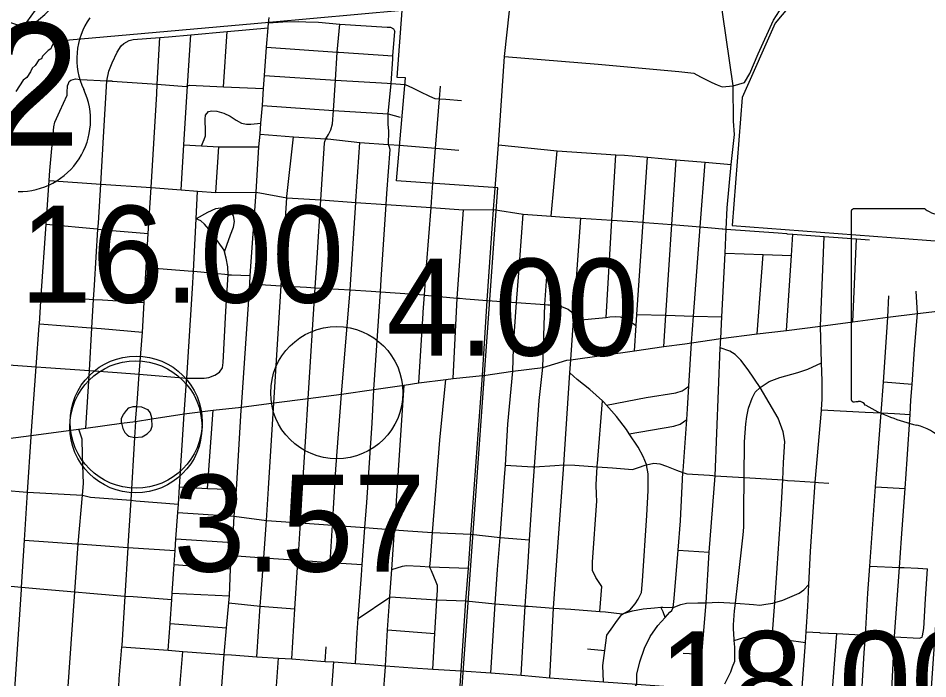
# Model space of a CAD drawing. Extents: x 1729596 to 1934326, y 644115 to 911751.
# Drawn here: x 1844605 to 1854923, y 714700 to 722193 of the extents above; entities that cross this region are included whole.
import ezdxf

# ---------------------------------------------------------------- set-up
doc = ezdxf.new("R2010")
doc.units = 0
for name, color, linetype in [('Default', 7, 'Continuous'), ('GM_X_City_Street', 7, 'Continuous'), ('GM_X_Corporation', 7, 'Continuous'), ('GM_X_Interstate_Route', 7, 'Continuous'), ('GM_X_State_Route', 7, 'Continuous'), ('GM_X_State_Shield', 7, 'Continuous'), ('GM_X_Township', 7, 'Continuous'), ('GM_X_US_Route', 7, 'Continuous'), ('GM_X_US_Shield', 7, 'Continuous')]:
    doc.layers.add(name, color=color, linetype=linetype)

msp = doc.modelspace()

# ---------------------------------------------------------------- linework, layer by layer
at = {"layer": 'Default'}
for centre in [(1848219, 717945), (1845943, 717611), (1845940, 717558)]:
    msp.add_circle(centre, 750, dxfattribs=at)
at = {"layer": 'GM_X_City_Street'}
for points in [[(1844681, 722118), (1844702, 722148), (1844900, 722425), (1844915, 722447), (1845042, 722635)], [(1852692, 720534), (1852732, 720874), (1852718, 721026), (1852717, 721427), (1852558, 722528)], [(1852717, 721427), (1852843, 721465), (1852904, 721564), (1852998, 721790), (1853173, 722172), (1853242, 722278), (1853303, 722358)], [(1844371, 722188), (1844574, 722127), (1844617, 722116), (1844681, 722118)], [(1847136, 717748), (1847138, 717780), (1847221, 719001), (1847231, 719179), (1847238, 719273), (1847303, 720218), (1847336, 720734), (1847351, 720879), (1847356, 721002), (1847375, 721204), (1847386, 721394), (1847399, 721545), (1847420, 721866), (1847442, 722083), (1847446, 722139), (1847451, 722196), (1847452, 722201)], [(1845863, 721939), (1845911, 721951), (1846211, 721973), (1846310, 721980), (1846564, 722004), (1846977, 722043), (1847442, 722083)], [(1847446, 722139), (1847607, 722150), (1847783, 722155), (1847869, 722153), (1848010, 722147), (1848254, 722126), (1848791, 722092), (1848827, 722091), (1848864, 722072), (1848878, 722043)], [(1848085, 720793), (1848094, 720826), (1848123, 720875), (1848152, 720925), (1848170, 720994), (1848181, 721145), (1848204, 721491), (1848225, 721808), (1848254, 722126)], [(1845953, 717827), (1845978, 718154), (1846015, 718631), (1846035, 718969), (1846058, 719366), (1846080, 719750), (1846115, 720271), (1846176, 721336), (1846182, 721443), (1846211, 721973)], [(1846452, 720248), (1846485, 720756), (1846527, 721426), (1846564, 722004)], [(1846932, 721415), (1846977, 722043)], [(1848854, 721731), (1848856, 721765), (1848878, 722043)], [(1845374, 717543), (1845413, 718196), (1845441, 718681), (1845461, 719004), (1845470, 719165), (1845510, 719801), (1845514, 719870), (1845541, 720311), (1845574, 720842), (1845612, 721484), (1845633, 721594), (1845670, 721688), (1845727, 721808), (1845773, 721879), (1845802, 721906), (1845863, 721939)], [(1847420, 721866), (1848225, 721808), (1848241, 721806)], [(1848241, 721806), (1848856, 721765)], [(1850016, 720267), (1850052, 720757), (1850121, 721758)], [(1850121, 721758), (1851183, 721671), (1852098, 721588), (1852268, 721570), (1852345, 721527), (1852473, 721462), (1852532, 721436), (1852590, 721416), (1852717, 721427)], [(1848812, 720742), (1848811, 720744), (1848809, 720753), (1848807, 720759), (1848811, 720910), (1848803, 720991), (1848803, 721108), (1848835, 721453), (1848854, 721731)], [(1844955, 720352), (1844965, 720464), (1845009, 720961), (1845020, 721012), (1845076, 721139), (1845161, 721321), (1845162, 721351), (1845166, 721425), (1845175, 721453), (1845185, 721475), (1845202, 721490), (1845256, 721507)], [(1845256, 721507), (1845312, 721499), (1845612, 721484), (1845656, 721481), (1845666, 721481), (1845672, 721480)], [(1845672, 721480), (1846182, 721443), (1846511, 721419), (1846527, 721426), (1846549, 721434), (1846932, 721415), (1847386, 721394)], [(1847399, 721545), (1848204, 721491), (1848789, 721456)], [(1848789, 721456), (1848835, 721453), (1848994, 721442)], [(1848994, 721442), (1849077, 721403), (1849162, 721360), (1849271, 721307), (1849332, 721283), (1849384, 721279), (1849456, 721274), (1849634, 721259)], [(1849307, 720321), (1849339, 720719), (1849384, 721279), (1849396, 721424)], [(1846685, 720744), (1846713, 720816), (1846729, 720860), (1846728, 720908), (1846724, 721046), (1846731, 721092), (1846765, 721135), (1846803, 721142), (1846857, 721139), (1846936, 721115), (1847009, 721080), (1847078, 721038), (1847139, 721003), (1847193, 720991), (1847243, 720990), (1847356, 721002)], [(1847375, 721204), (1848181, 721145), (1848803, 721108), (1848939, 721072)], [(1847351, 720879), (1847728, 720849), (1848094, 720826), (1848116, 720823)], [(1847504, 717831), (1847589, 719157), (1847589, 719159), (1847653, 720157), (1847654, 720169), (1847728, 720849)], [(1846485, 720756), (1846685, 720744), (1846879, 720733), (1847336, 720734)], [(1846848, 720217), (1846879, 720733)], [(1847894, 717880), (1847974, 719135), (1847996, 719475), (1848038, 720131), (1848080, 720775), (1848085, 720793)], [(1848116, 720823), (1848480, 720782), (1848803, 720759), (1848807, 720759), (1848931, 720752)], [(1848435, 720107), (1848435, 720117), (1848480, 720782)], [(1848640, 717983), (1848714, 719090), (1848723, 719230), (1848779, 720080), (1848787, 720204), (1848823, 720702), (1848812, 720742)], [(1848931, 720752), (1849339, 720719), (1849604, 720698)], [(1850052, 720757), (1850720, 720687), (1851385, 720644), (1851481, 720638), (1851742, 720615), (1852070, 720587), (1852396, 720559), (1852692, 720534)], [(1850652, 719946), (1850720, 720687)], [(1851343, 719959), (1851343, 719959), (1851385, 720644)], [(1851697, 719936), (1851697, 719936), (1851742, 720615)], [(1851930, 718468), (1851953, 718823), (1852021, 719852), (1852070, 720587)], [(1852241, 718512), (1852264, 718814), (1852341, 719825), (1852396, 720559)], [(1852570, 718492), (1852572, 718519), (1852574, 718560), (1852586, 718804), (1852623, 719527), (1852637, 719801), (1852649, 720043), (1852692, 720534)], [(1844752, 717444), (1844753, 717461), (1844810, 718238), (1844844, 718706), (1844846, 718726), (1844867, 719046), (1844922, 719856), (1844955, 720352)], [(1844955, 720352), (1845541, 720311), (1846115, 720271), (1846452, 720248), (1846640, 720233), (1846848, 720217), (1847303, 720218)], [(1849294, 720111), (1849294, 720112), (1849307, 720321)], [(1846514, 718074), (1846516, 718110), (1846584, 719128), (1846593, 719322), (1846624, 719917), (1846640, 720233)], [(1847303, 720218), (1847653, 720157), (1848038, 720131), (1848435, 720104), (1848779, 720080), (1849290, 720045), (1849657, 720020), (1849998, 720023)], [(1849872, 718141), (1849926, 718992), (1849998, 720023), (1850016, 720267)], [(1848272, 717930), (1848370, 719111), (1848435, 720104), (1848435, 720107)], [(1849238, 719374), (1849238, 719381), (1849290, 720045), (1849294, 720111)], [(1846945, 719543), (1846970, 719620), (1847013, 719735), (1847048, 719824), (1847058, 719886), (1847046, 719952), (1847019, 719995), (1846987, 720018), (1846954, 720033), (1846902, 720039), (1846844, 720032), (1846754, 719991), (1846624, 719917)], [(1849538, 718108), (1849586, 719019), (1849657, 720020)], [(1849998, 720023), (1850334, 719971), (1850652, 719946), (1850799, 719935), (1850987, 719923), (1851340, 719901), (1851693, 719879), (1851715, 719877), (1852021, 719852), (1852341, 719825), (1852470, 719814), (1852590, 719805), (1852598, 719804)], [(1846516, 718110), (1846632, 718110), (1846714, 718110), (1846766, 718118), (1846837, 718144), (1846888, 718179), (1846923, 718228), (1846931, 718288), (1846962, 718870), (1846986, 719285), (1846983, 719373), (1846965, 719470), (1846945, 719543), (1846940, 719561), (1846873, 719657), (1846794, 719769), (1846719, 719858), (1846678, 719895), (1846624, 719917)], [(1850294, 719447), (1850295, 719457), (1850334, 719971)], [(1850873, 718319), (1850905, 718763), (1850987, 719923)], [(1851273, 718800), (1851340, 719901), (1851343, 719959)], [(1851596, 718421), (1851615, 718709), (1851624, 718834), (1851693, 719879), (1851697, 719936)], [(1844922, 719856), (1845501, 719802)], [(1845501, 719802), (1845503, 719802), (1845510, 719801), (1845582, 719794), (1846080, 719750)], [(1852598, 719804), (1852637, 719801), (1853225, 719757), (1853319, 719750), (1853326, 719749)], [(1853319, 718652), (1853376, 719500), (1853393, 719744)], [(1853326, 719749), (1853393, 719744), (1853749, 719718), (1854114, 719690), (1854263, 719679)], [(1853705, 718700), (1853749, 719718)], [(1854074, 718749), (1854114, 719690)], [(1852623, 719527), (1853056, 719511), (1853376, 719500)], [(1852988, 718611), (1853056, 719511)], [(1850222, 718452), (1850222, 718481), (1850259, 718970), (1850294, 719447)], [(1850555, 718232), (1850579, 718947), (1850612, 719423)], [(1846058, 719366), (1846582, 719323), (1846593, 719322), (1846594, 719322)], [(1846594, 719322), (1846677, 719316), (1846986, 719285), (1846992, 719284), (1847003, 719284), (1847023, 719283)], [(1847023, 719283), (1847238, 719273)], [(1849198, 718847), (1849199, 718859), (1849213, 719054), (1849238, 719374)], [(1847231, 719179), (1847589, 719157), (1847874, 719141), (1847974, 719135), (1848370, 719111), (1848610, 719097), (1848714, 719090), (1849213, 719054), (1849219, 719053), (1849586, 719019), (1849597, 719018), (1849609, 719017)], [(1854805, 718842), (1854792, 719098)], [(1844867, 719046), (1845461, 719004), (1845563, 718997), (1846035, 718969)], [(1849609, 719017), (1849682, 719010), (1849926, 718992)], [(1849926, 718992), (1850259, 718970), (1850579, 718947), (1850582, 718947), (1850613, 718943), (1850631, 718940)], [(1854469, 718802), (1854481, 719044)], [(1850631, 718940), (1850668, 718934), (1850756, 718926), (1850843, 718891), (1850886, 718858), (1850905, 718763), (1851273, 718800), (1851315, 718804), (1851375, 718810), (1851435, 718807), (1851510, 718774), (1851615, 718709)], [(1849150, 718057), (1849198, 718847)], [(1851624, 718834), (1851953, 718823), (1852264, 718814), (1852586, 718804)], [(1854170, 714483), (1854202, 714993), (1854215, 715195), (1854244, 715671), (1854265, 715979), (1854331, 716879), (1854393, 717715), (1854393, 717717), (1854422, 718065), (1854469, 718802)], [(1854397, 712816), (1854440, 713426), (1854449, 713558), (1854471, 713904), (1854506, 714424), (1854546, 715177), (1854546, 715183), (1854601, 715963), (1854624, 716297), (1854666, 716858), (1854690, 717192), (1854722, 717698), (1854732, 717860), (1854745, 718038), (1854774, 718438), (1854805, 718842)], [(1844846, 718726), (1845429, 718682), (1845431, 718682)], [(1845431, 718682), (1845441, 718681), (1845546, 718673), (1846015, 718631)], [(1853332, 713071), (1853334, 713085), (1853400, 713513), (1853435, 713744), (1853452, 713957), (1853492, 714498), (1853536, 715110), (1853544, 715232), (1853563, 715520), (1853574, 715770), (1853591, 716145), (1853644, 716930), (1853716, 717743), (1853716, 717751), (1853725, 717875), (1853725, 718079), (1853719, 718283), (1853705, 718700)], [(1852034, 715508), (1852047, 715612), (1852090, 716158), (1852116, 716492), (1852146, 717041), (1852147, 717059), (1852188, 717640), (1852197, 717763), (1852212, 718019), (1852241, 718512)], [(1852193, 712911), (1852193, 712911), (1852252, 713596), (1852333, 714585), (1852361, 714976), (1852409, 715561), (1852442, 716135), (1852511, 717004), (1852568, 718454), (1852570, 718492)], [(1853156, 715168), (1853187, 715565), (1853192, 715623), (1853259, 716622), (1853277, 716955), (1853288, 717154), (1853301, 717392), (1853282, 717503), (1853225, 717655), (1853023, 718003), (1852884, 718206), (1852802, 718314), (1852739, 718380), (1852678, 718416), (1852568, 718454)], [(1842933, 718358), (1844447, 718264), (1844810, 718238), (1844918, 718230), (1845413, 718196), (1845727, 718175), (1845978, 718154), (1846516, 718110)], [(1850216, 718190), (1850222, 718452)], [(1850635, 714711), (1850676, 715502), (1850713, 715988), (1850793, 717127), (1850805, 717306), (1850862, 718172), (1850873, 718319)], [(1853023, 718003), (1853125, 718071), (1853244, 718119), (1853448, 718174), (1853561, 718212), (1853719, 718283)], [(1849965, 714766), (1850014, 715550), (1850043, 715939), (1850071, 716303), (1850123, 716985), (1850132, 717123), (1850161, 717589), (1850216, 718190)], [(1850310, 714742), (1850340, 715271), (1850356, 715525), (1850388, 716023), (1850404, 716277), (1850445, 716897), (1850460, 717104), (1850513, 717857), (1850555, 718232)], [(1851243, 714665), (1851236, 714852), (1851260, 715021), (1851284, 715195), (1851349, 715291), (1851391, 715350), (1851451, 715429), (1851473, 715441), (1851543, 715480), (1851603, 715551), (1851638, 715604), (1851674, 715679), (1851686, 715811), (1851736, 716553), (1851752, 716835), (1851751, 716946), (1851750, 717026), (1851733, 717128), (1851733, 717131), (1851693, 717222), (1851638, 717326), (1851537, 717478), (1851504, 717528), (1851392, 717674), (1851277, 717804), (1851239, 717846), (1851233, 717852), (1851091, 717983), (1850946, 718096), (1850862, 718172)], [(1846489, 717706), (1846514, 718074)], [(1849310, 714808), (1849332, 715214), (1849354, 715596), (1849360, 715704), (1849361, 715760), (1849348, 715795), (1849292, 715926), (1849275, 715963), (1849276, 715969), (1849282, 716051), (1849306, 716359), (1849389, 717405), (1849454, 718095)], [(1849508, 713010), (1849533, 713412), (1849555, 713758), (1849581, 714093), (1849583, 714126), (1849607, 714451), (1849629, 714791), (1849684, 715585), (1849714, 715954), (1849739, 716340), (1849872, 718141)], [(1854745, 718038), (1854422, 718065)], [(1848537, 716414), (1848537, 716415), (1848558, 716699), (1848622, 717598), (1848640, 717983)], [(1848673, 713046), (1848673, 713047), (1848705, 713425), (1848705, 713426), (1848708, 713773), (1848708, 713794), (1848725, 714152), (1848730, 714259), (1848746, 714487), (1848770, 714837), (1848771, 714847), (1848796, 715255), (1848819, 715627), (1848819, 715633), (1848842, 715938), (1848874, 716390), (1848889, 716600), (1848926, 717180), (1848982, 718032)], [(1851277, 717804), (1851727, 717891), (1852066, 717943), (1852135, 717967), (1852170, 717990), (1852212, 718019)], [(1852619, 714643), (1852687, 714778), (1852707, 714837), (1852733, 714901), (1852733, 714975), (1852733, 715057), (1852728, 715133), (1852728, 715146), (1852719, 715272), (1852718, 715312), (1852729, 715472), (1852742, 715556), (1852770, 715794), (1852828, 716333), (1852835, 716421), (1852836, 716616), (1852839, 716976), (1852839, 716985), (1852843, 717387), (1852857, 717593), (1852869, 717677), (1852890, 717771), (1852931, 717882), (1852963, 717951), (1853023, 718003)], [(1847777, 716024), (1847779, 716045), (1847806, 716468), (1847823, 716745), (1847869, 717447), (1847894, 717880)], [(1848170, 716442), (1848209, 717078), (1848272, 717930)], [(1851173, 717118), (1851173, 717120), (1851175, 717141), (1851233, 717852)], [(1845778, 717598), (1845778, 717656), (1845801, 717699), (1845835, 717744), (1845860, 717774), (1845910, 717788), (1845950, 717789), (1846004, 717786), (1846071, 717754), (1846102, 717717), (1846111, 717692), (1846121, 717649)], [(1845937, 717620), (1845950, 717789), (1845953, 717827)], [(1846754, 716857), (1846818, 717746)], [(1846836, 713122), (1846840, 713500), (1846863, 713873), (1846886, 714244), (1846887, 714257), (1846915, 714615), (1846942, 714976), (1846966, 715278), (1846996, 715563), (1847001, 715640), (1847015, 715946), (1847031, 716098), (1847038, 716245), (1847054, 716543), (1847080, 716846), (1847136, 717748)], [(1847311, 714951), (1847351, 715524), (1847361, 715666), (1847390, 716073), (1847416, 716446), (1847420, 716496), (1847444, 716860), (1847504, 717831)], [(1853716, 717751), (1854211, 717723), (1854393, 717715), (1854547, 717709), (1854722, 717698)], [(1845778, 717598), (1845791, 717539), (1845814, 717493), (1845841, 717466), (1845860, 717451), (1845926, 717437), (1846010, 717443), (1846067, 717477), (1846109, 717522), (1846126, 717564), (1846121, 717649)], [(1846308, 715024), (1846329, 715327), (1846348, 715598), (1846353, 715673), (1846375, 715997), (1846386, 716155), (1846395, 716289), (1846416, 716585), (1846422, 716681), (1846436, 716879), (1846489, 717706)], [(1851537, 717478), (1852043, 717565), (1852114, 717587), (1852151, 717616), (1852188, 717640)], [(1845118, 713864), (1845247, 715686), (1845274, 716069), (1845285, 716229), (1845335, 716782), (1845345, 716914), (1845339, 717125), (1845333, 717241), (1845329, 717419), (1845294, 717532)], [(1844472, 713184), (1844520, 713906), (1844642, 715713), (1844644, 715740), (1844677, 716273), (1844712, 716818), (1844752, 717444)], [(1850132, 717123), (1850443, 717104), (1850450, 717104)], [(1850450, 717104), (1850453, 717104), (1850460, 717104), (1850694, 717121), (1850793, 717127), (1850798, 717128), (1850920, 717122), (1851172, 717105), (1851345, 717094), (1851573, 717075), (1851629, 717092), (1851728, 717127), (1851733, 717128), (1851817, 717146), (1851883, 717140), (1851958, 717112), (1852071, 717067), (1852146, 717041), (1852190, 717025), (1852446, 717009), (1852483, 717006)], [(1851204, 715463), (1851224, 715746), (1851157, 715850), (1851121, 715928), (1851120, 716024), (1851168, 716720), (1851164, 716786), (1851160, 716905), (1851172, 717105), (1851173, 717118)], [(1852483, 717006), (1852511, 717004), (1852839, 716985), (1852843, 716984), (1853277, 716955), (1853282, 716955), (1853330, 716951)], [(1853330, 716951), (1853412, 716946), (1853644, 716930), (1853683, 716927)], [(1853683, 716927), (1853802, 716919)], [(1844439, 716839), (1844707, 716818)], [(1844707, 716818), (1844707, 716818), (1844712, 716818), (1845335, 716782), (1845426, 716762), (1845881, 716725), (1845940, 716720)], [(1846436, 716879), (1846754, 716857), (1847080, 716846)], [(1854331, 716879), (1854666, 716858)], [(1845940, 716720), (1845940, 716720), (1846422, 716681)], [(1846416, 716585), (1847049, 716543)], [(1847049, 716543), (1847054, 716543), (1847420, 716496), (1847806, 716468), (1848170, 716442), (1848274, 716435), (1848537, 716415), (1848874, 716390), (1849025, 716379), (1849306, 716359), (1849739, 716340)], [(1848142, 716020), (1848170, 716442)], [(1848431, 714872), (1848451, 715227), (1848463, 715383), (1848498, 715877), (1848507, 715995), (1848537, 716414)], [(1846395, 716289), (1847038, 716245)], [(1849739, 716340), (1850071, 716303), (1850404, 716277)], [(1844677, 716273), (1845265, 716231)], [(1845265, 716231), (1845265, 716231), (1845285, 716229), (1845848, 716191), (1846386, 716155)], [(1847031, 716098), (1847390, 716073), (1847779, 716045), (1847841, 716041), (1848142, 716020), (1848507, 715995)], [(1852090, 716158), (1852442, 716135)], [(1846375, 715997), (1847015, 715946)], [(1847708, 714925), (1847744, 715494), (1847777, 716024)], [(1848842, 715938), (1848963, 715978), (1849008, 715987), (1849166, 715978), (1849276, 715969), (1849714, 715954)], [(1854265, 715979), (1854601, 715963), (1854646, 715961), (1854654, 715961)], [(1854654, 715961), (1854809, 715953), (1854812, 715953)], [(1854812, 715953), (1854918, 715948)], [(1854860, 715174), (1854862, 715186), (1854877, 715272), (1854897, 715607), (1854918, 715948)], [(1844359, 715765), (1844644, 715740), (1844852, 715722), (1845247, 715686), (1845418, 715670), (1845814, 715639), (1845910, 715632), (1846348, 715598)], [(1846353, 715673), (1847001, 715640)], [(1850389, 715523), (1850676, 715502), (1850874, 715488), (1851204, 715463), (1851268, 715458), (1851457, 715437), (1851473, 715441), (1851572, 715470), (1851695, 715492), (1851824, 715506), (1851893, 715512), (1851918, 715514), (1852034, 715508), (1852121, 715542), (1852185, 715556), (1852313, 715562), (1852409, 715561), (1852546, 715568), (1852742, 715556), (1852746, 715556), (1852947, 715542), (1853019, 715536), (1853085, 715546), (1853164, 715558), (1853187, 715565), (1853279, 715593), (1853463, 715672), (1853516, 715708), (1853574, 715770)], [(1848463, 715383), (1848819, 715627), (1848825, 715631), (1849354, 715596), (1849684, 715585)], [(1849684, 715585), (1850014, 715550), (1850356, 715525), (1850370, 715524), (1850389, 715523)], [(1846996, 715563), (1847351, 715524), (1847744, 715494)], [(1851602, 714585), (1851606, 714616), (1851621, 714638), (1851624, 714753), (1851656, 714892), (1851708, 715049), (1851774, 715181), (1851860, 715303), (1851944, 715396), (1851996, 715457), (1852021, 715475), (1852034, 715508)], [(1851944, 715396), (1851920, 715460), (1851893, 715512)], [(1846329, 715327), (1846966, 715278)], [(1848796, 715255), (1849332, 715214)], [(1852728, 715133), (1852838, 715170), (1852939, 715188), (1853005, 715192), (1853127, 715172), (1853156, 715168), (1853322, 715142), (1853536, 715110)], [(1853544, 715232), (1853693, 715224)], [(1853693, 715224), (1853702, 715223), (1853892, 715212), (1854162, 715197)], [(1853720, 712844), (1853766, 713483), (1853780, 713680), (1853798, 713937), (1853831, 714475), (1853840, 714526), (1853892, 715212)], [(1854162, 715197), (1854215, 715195), (1854539, 715177)], [(1854539, 715177), (1854546, 715177), (1854829, 715161), (1854860, 715174)], [(1845778, 715063), (1846308, 715024), (1846472, 715011), (1846942, 714976), (1847025, 714970), (1847311, 714951), (1847556, 714935), (1847708, 714925), (1847894, 714913), (1848086, 714898), (1848184, 714891), (1848431, 714872), (1848639, 714857), (1848771, 714847), (1849078, 714824), (1849310, 714808), (1849629, 714791)], [(1848086, 714898), (1848098, 715063)], [(1846330, 713130), (1846359, 713520), (1846388, 713900), (1846417, 714283), (1846444, 714646), (1846472, 715011)], [(1851062, 715039), (1851260, 715021)], [(1852361, 714976), (1852147, 714988)], [(1847535, 714618), (1847556, 714935)], [(1848043, 713060), (1848072, 713449), (1848099, 713804), (1848104, 713862), (1848131, 714186), (1848149, 714408), (1848158, 714528), (1848184, 714891)], [(1849629, 714791), (1849965, 714766), (1850310, 714742), (1850635, 714711), (1850889, 714691), (1851243, 714665), (1851621, 714638), (1852333, 714585), (1852608, 714566), (1852749, 714535), (1852864, 714527), (1853154, 714509), (1853333, 714499), (1853492, 714498), (1853831, 714475), (1854168, 714448), (1854506, 714424), (1854776, 714403), (1854803, 714408)]]:
    msp.add_lwpolyline(points, dxfattribs=at)
at = {"layer": 'GM_X_Corporation'}
for points in [[(1864915, 723684), (1853770, 722829), (1853193, 722137), (1852817, 721295), (1852704, 719841), (1855309, 719646), (1854937, 714267), (1854865, 713813), (1854855, 713472), (1854981, 713123), (1855053, 712757), (1854973, 711528), (1864435, 710746)], [(1849283, 709587), (1850045, 720270), (1848895, 720350), (1849000, 721518), (1848903, 721522), (1848959, 722281), (1847451, 722146), (1845017, 721929), (1845007, 721909), (1844986, 721877), (1844975, 721846), (1844944, 721825), (1844912, 721793), (1844881, 721762), (1844870, 721731), (1844839, 721720), (1844797, 721657), (1844765, 721626), (1844744, 721584), (1844703, 721521), (1844661, 721489), (1844577, 721363)]]:
    msp.add_lwpolyline(points, dxfattribs=at)
at = {"layer": 'GM_X_Interstate_Route'}
msp.add_lwpolyline([(1844253, 721884), (1844460, 721950), (1844593, 722011), (1844703, 722070), (1844764, 722113), (1844907, 722235), (1845015, 722350), (1845072, 722430), (1845119, 722516), (1845218, 722738), (1845247, 722822), (1845271, 722878), (1845310, 723020), (1845361, 723206), (1845429, 723467)], dxfattribs=at)
at = {"layer": 'GM_X_State_Route'}
for points in [[(1849883, 718142), (1850216, 718190), (1850555, 718232), (1850829, 718313), (1850873, 718319), (1851596, 718421), (1851930, 718468), (1852168, 718501), (1852241, 718512), (1852574, 718560), (1852988, 718611), (1853319, 718652), (1853705, 718700), (1854074, 718749), (1854469, 718802), (1854805, 718842), (1855227, 718891), (1855228, 718891)], [(1845937, 717620), (1846121, 717649), (1846489, 717706), (1846818, 717746), (1847138, 717780), (1847504, 717831), (1847894, 717880), (1848272, 717930), (1848640, 717983), (1848982, 718032), (1849150, 718057), (1849454, 718095), (1849538, 718108), (1849872, 718141), (1849883, 718142)]]:
    msp.add_lwpolyline(points, dxfattribs=at)
at = {"layer": 'GM_X_State_Shield'}
for p, q in [((1854895, 720029), (1854080, 720029)), ((1854052, 719993), (1854052, 717879))]:
    msp.add_line(p, q, dxfattribs=at)
for centre, radius, start, end in [((1854084, 719997), 32.3, 98.1301, 188.1301), ((1855089, 720274), 313, 231.6195, 271.1119), ((1854084, 717875), 32.5, 171.9584, 258.3066), ((1854089, 718091), 248, 267.339, 280.6039), ((1854140, 717757), 89.5, 29.7484, 93.2717), ((1855271, 719656), 2132, 240.4129, 257.1985), ((1854635, 716930), 667, 47.1842, 75.836)]:
    msp.add_arc(centre, radius, start, end, dxfattribs=at)
at = {"layer": 'GM_X_Township'}
msp.add_lwpolyline([(1849607, 714451), (1849629, 714791), (1849684, 715585), (1849714, 715954), (1849739, 716340), (1849872, 718141), (1849926, 718991), (1849998, 720023), (1850016, 720267), (1850052, 720757), (1850121, 721758), (1850232, 722763), (1852558, 722529), (1860402, 721998), (1860890, 721958), (1861185, 721935), (1864108, 721712)], dxfattribs=at)
at = {"layer": 'GM_X_US_Route'}
for points in [[(1844491, 717426), (1844753, 717461), (1845290, 717532), (1845294, 717532), (1845374, 717543), (1845778, 717598), (1845937, 717620)], [(1845937, 717620), (1845926, 717437), (1845881, 716727)], [(1845881, 716727), (1845881, 716725), (1845849, 716208), (1845848, 716191), (1845814, 715639), (1845779, 715076), (1845778, 715063), (1845746, 714701), (1845745, 714685), (1845723, 714322), (1845701, 713949), (1845701, 713940), (1845694, 713824), (1845685, 713680)]]:
    msp.add_lwpolyline(points, dxfattribs=at)
at = {"layer": 'GM_X_US_Shield'}
for centre, start, end in [((1846082, 721733), 144.9991, 205.4529), ((1844614, 721038), 269.3617, 25.1681)]:
    msp.add_arc(centre, 812, start, end, dxfattribs=at)

# ---------------------------------------------------------------- texts
at = {"layer": 'Default'}
for s, p in [('16.00', (1844622, 718966)), ('4.00', (1848781, 718366)), ('3.57', (1846364, 715916)), ('18.00', (1851870, 714140))]:
    msp.add_text(s, height=1100, dxfattribs=at).set_placement(p)
at = {"layer": 'GM_X_US_Shield'}
msp.add_text('62', height=1392.2, dxfattribs=at).set_placement((1843237, 720748))

doc.saveas('drawing.dxf')
